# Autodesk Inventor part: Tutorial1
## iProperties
Shininess: 64.0
Length Units: 11269
Angle Units: 11279
Time Units: 11290
Mass Units: 11283
Length Display Precision: 3
Angle Display Precision: 2
Compacted: True
Part Number: Tutorial1
Document SubType Name: Modeling
Created: 2002-11
Designer: deepak
Density: 1 g/cm^3
Density: 0.0
Volumn: 0.0
Area: 0.0
PropertySet Name: Model Information
Control State: 0
Master: False
Checked Out: False
Author: deepak
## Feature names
1. Extrusion1
